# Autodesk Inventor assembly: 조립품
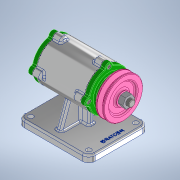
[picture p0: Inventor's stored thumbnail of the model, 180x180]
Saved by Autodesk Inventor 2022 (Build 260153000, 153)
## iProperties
Created: 2023-05
Part Number: 조립품
Document SubType Name: Assembly
Designer: Admin
Author: Admin
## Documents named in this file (12)
- C:\Users\Admin\Desktop\730508V1007\조립품.iam
- C:\Users\Admin\Desktop\730508V1007\본체.ipt
- C:\Users\Admin\Desktop\730508V1007\개스킷.ipt
- C:\Users\Admin\Desktop\730508V1007\앞커버.ipt
- C:\Users\Admin\Desktop\730508V1007\뒤커버.ipt
- C:\Users\Admin\Desktop\730508V1007\베어링 6204.ipt
- C:\Users\Admin\Desktop\730508V1007\오일 실.ipt
- C:\Users\Admin\Desktop\730508V1007\축.ipt
- C:\Users\Admin\Desktop\730508V1007\볼트 M4 x 12.ipt
- C:\Users\Admin\Desktop\730508V1007\키 4 x 4.ipt
- C:\Users\Admin\Desktop\730508V1007\V-벨트풀리.ipt
- C:\Users\Admin\Desktop\730508V1007\너트 M12 x 1.25.ipt
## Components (8 placed, 6 different names)
1. 개스킷:1
2. 개스킷:2
3. KS B 2804 D D - 20 32 8:1
4. KS B 1311 (I) 4 x 4 x 12:1
5. V-벨트풀리:1
6. KS B 1012 클래스 1 일반 - 미터 M12x1.25:1
7. KS B 2023 6204 - 20 x 47 x 14:1
8. KS B 2023 6204 - 20 x 47 x 14:2
